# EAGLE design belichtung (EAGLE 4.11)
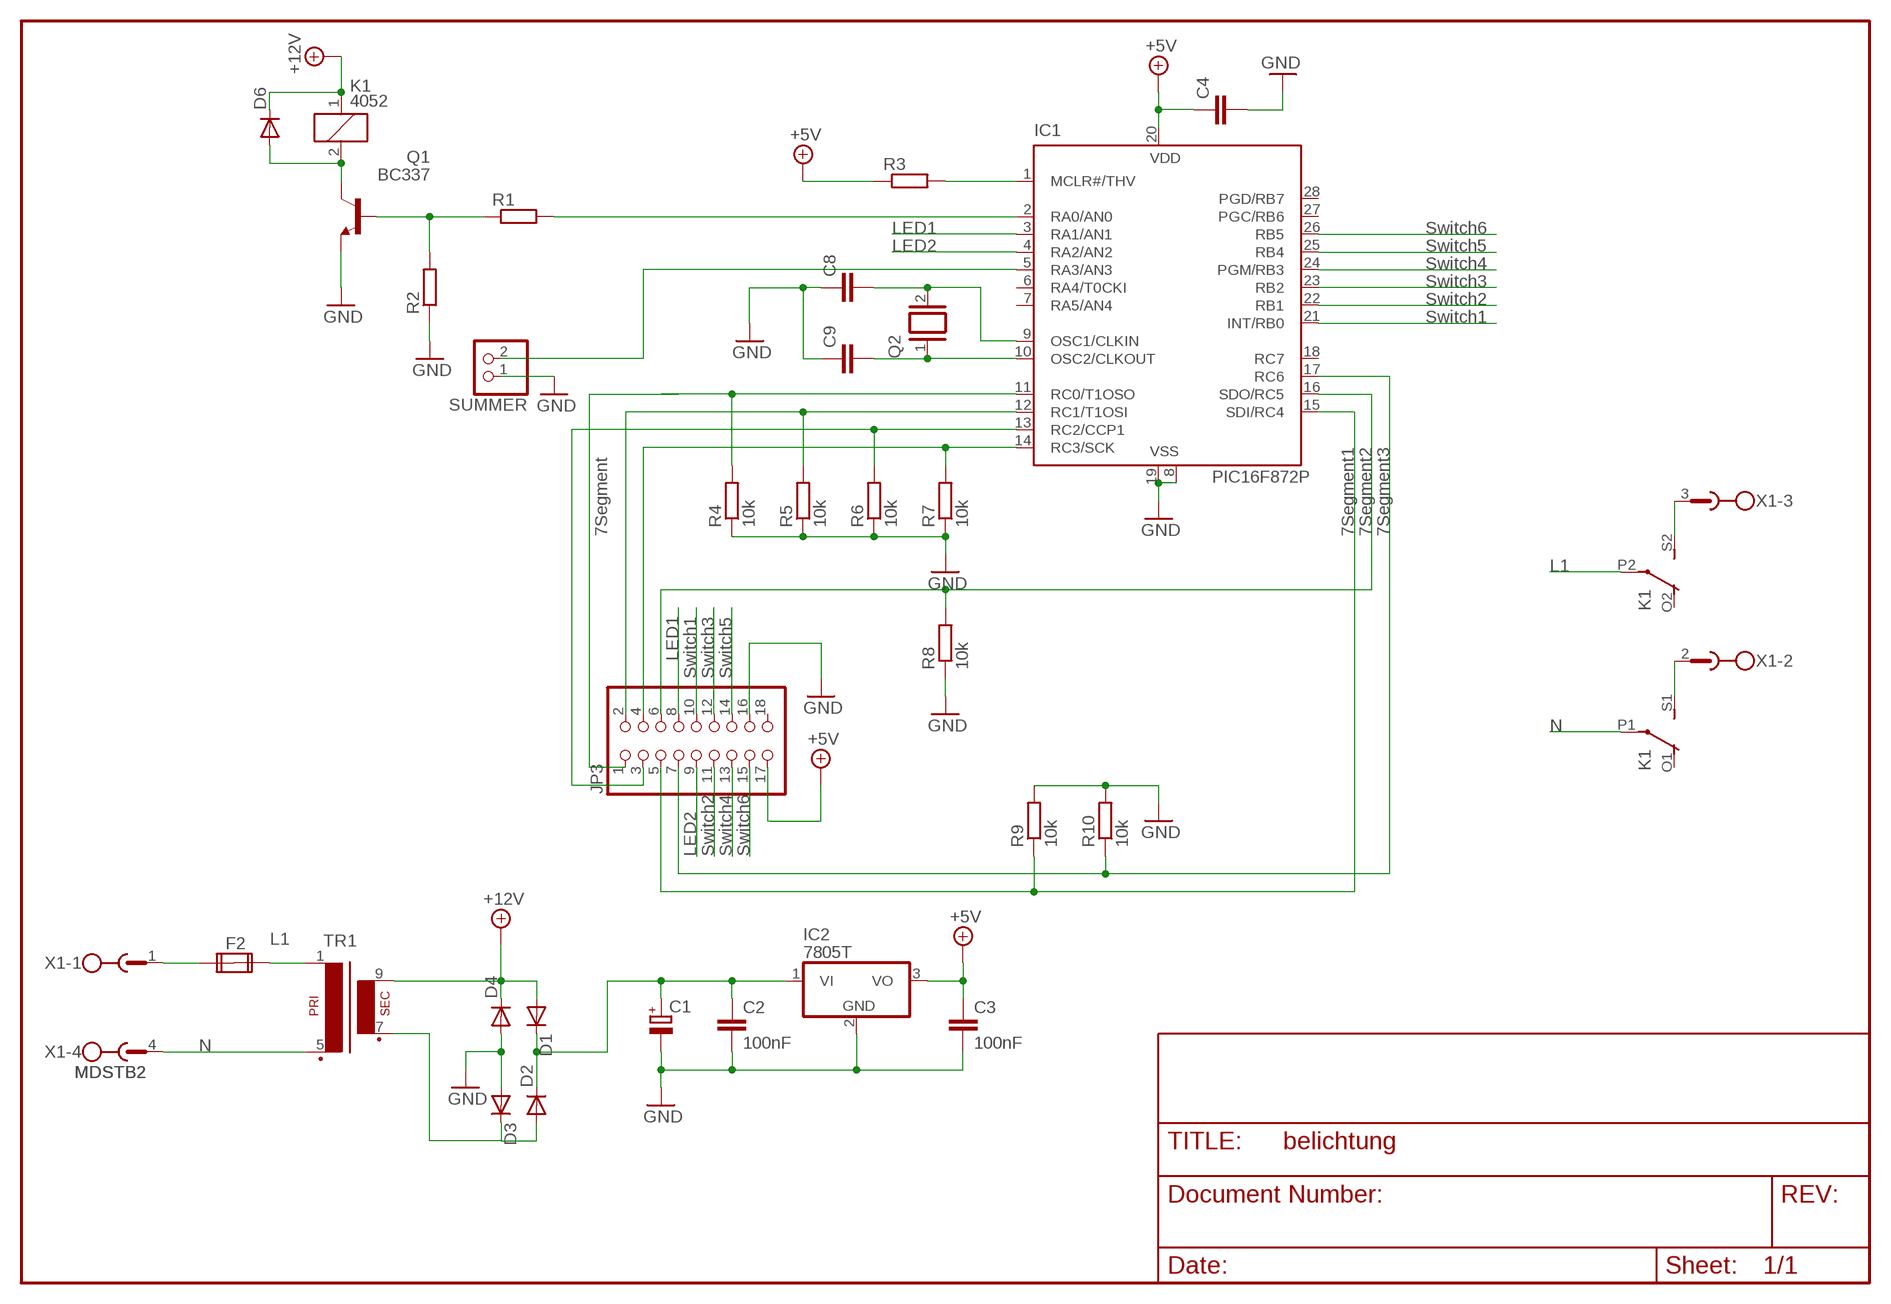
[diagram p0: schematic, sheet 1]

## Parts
C1  CPOL-EUE3.5-8  [E3,5-8]
C2  100nF  C10/4  [C10B4]
C3  100nF  C10/4  [C10B4]
C4  C-EUC1206K  [C1206K]
C8  C-EUC1206K  [C1206K]
C9  C-EUC1206K  [C1206K]
D1  1N4004  [DO41-10]
D2  1N4004  [DO41-10]
D3  1N4004  [DO41-10]
D4  1N4004  [DO41-10]
D6  DIODE-SMB  [SMB]
F2  FUSE2P  [FUSE1]
IC1  PIC16F872P  [DIL28-3]
IC2  7805T  [TO220H]
JP3  PINHD-2X9  [2X09]
K1  4052  [F4052]
Q1  BC337  [TO92]
Q2  XTAL  [Q]
R1  R-EU_0204/7  [0204/7]
R2  R-EU_0204/7  [0204/7]
R3  R-EU_0204/7  [0204/7]
R4  10k  R-EU_R0805  [R0805]
R5  10k  R-EU_0204/7  [0204/7]
R6  10k  R-EU_0204/7  [0204/7]
R7  10k  R-EU_0204/7  [0204/7]
R8  10k  R-EU_R1206  [R1206]
R9  10k  R-EU_0204/2V  [0204V]
R10  10k  R-EU_0204/7  [0204/7]
SUMMER  PINHD-1X2  [1X02]
TR1  EI30-1  [EI30-1]
X1  MDSTB2  [MDSTB2]

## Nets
+5V: C3.1 C4.1 IC1.20(VDD) IC2.3(VO) JP3.17 R3.1
+12V: D1.A D4.C D6.C K1.1 TR1.9
GND: C1.- C2.2 C3.2 C4.2 C8.1 C9.1 D3.A D4.A IC1.8(VSS) IC1.19(VSS) IC2.2(GND) JP3.16 Q1.1(E) R2.1 R4.1 R5.1 R6.1 R7.1 R8.1 R9.2 R10.2 SUMMER.1
IN: F2.1A X1.1
L1: F2.2A K1.P2(3:P) TR1.1
LED1: IC1.3(RA1/AN1) JP3.8
LED2: IC1.4(RA2/AN2) JP3.9
MCLR: IC1.1(MCLR#/THV) R3.2
N: K1.P1(2:P) TR1.5 X1.4
N$1: IC1.11(RC0/T1OSO) JP3.1 R4.2
N$2: Q1.2(B) R1.1 R2.2
N$3: IC1.13(RC2/CCP1) JP3.3 R6.2
N$5: IC1.16(SDO/RC5) JP3.6 R8.2
N$6: IC1.14(RC3/SCK) JP3.4 R7.2
N$7: K1.S1(2:S) X1.2
N$8: IC1.2(RA0/AN0) R1.2
N$10: IC1.15(SDI/RC4) JP3.5 R9.1
N$12: IC1.17(RC6) JP3.7 R10.1
N$19: IC1.5(RA3/AN3) SUMMER.2
N$20: C1.+ C2.1 D1.C D2.C IC2.1(VI)
N$21: IC1.12(RC1/T1OSI) JP3.2 R5.2
N$25: K1.S2(3:S) X1.3
N$27: D2.A D3.C TR1.7
N$29: C9.2 IC1.10(OSC2/CLKOUT) Q2.1
N$30: D6.A K1.2 Q1.3(C)
N$33: C8.2 IC1.9(OSC1/CLKIN) Q2.2
SWITCH1: IC1.21(INT/RB0) JP3.10
SWITCH2: IC1.22(RB1) JP3.11
SWITCH3: IC1.23(RB2) JP3.12
SWITCH4: IC1.24(PGM/RB3) JP3.13
SWITCH5: IC1.25(RB4) JP3.14
SWITCH6: IC1.26(RB5) JP3.15
Unconnected: F2.1B F2.2B IC1.6(RA4/T0CKI) IC1.7(RA5/AN4) IC1.18(RC7) IC1.27(PGC/RB6) IC1.28(PGD/RB7) JP3.18 K1.O1(2:O) K1.O2(3:O)

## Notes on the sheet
- LED1 | Switch6
- LED2 | Switch5
- Switch4
- Switch3
- Switch2
- Switch1
- 7Segment | 7Segment1 | 7Segment2 | 7Segment3
- L1
- LED1
- Switch1 | Switch3 | Switch5
- N
- LED2 | Switch2 | Switch4 | Switch6
- L1
- N

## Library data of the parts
C1 = rcl:CPOL-EU: POLARIZED CAPACITOR, European symbol
C2 C3 = capacitor-wima:C: CAPACITOR
C4 C8 C9 = rcl:C-EU: CAPACITOR, European symbol
D1-D4 = diode:1N4004: DIODE
D6 = diode:DIODE-: DIODE
F2 = special:FUSE2P: FUSE 5 x 20 mm
IC1 = microchip:PIC16*872: MICROCONTROLLER flash type
IC2 = linear:78*: Positive VOLTAGE REGULATOR
JP3 = pinhead:PINHD-2X9: PIN HEADER
K1 = relay:4052: RELAY 2 x switch, Finder
Q1 = transistor-npn:BC337*: NPN Transistor
Q2 = special:XTAL: CRYSTAL
R1-R10 = rcl:R-EU_: RESISTOR, European symbol
SUMMER = pinhead:PINHD-1X2: PIN HEADER
TR1 = trafo:EI30-1: TRANSFORMER 1 primary winding, 1 secondary winding ERA
X1 = con-phoenix-508:MDSTB2: PHOENIX

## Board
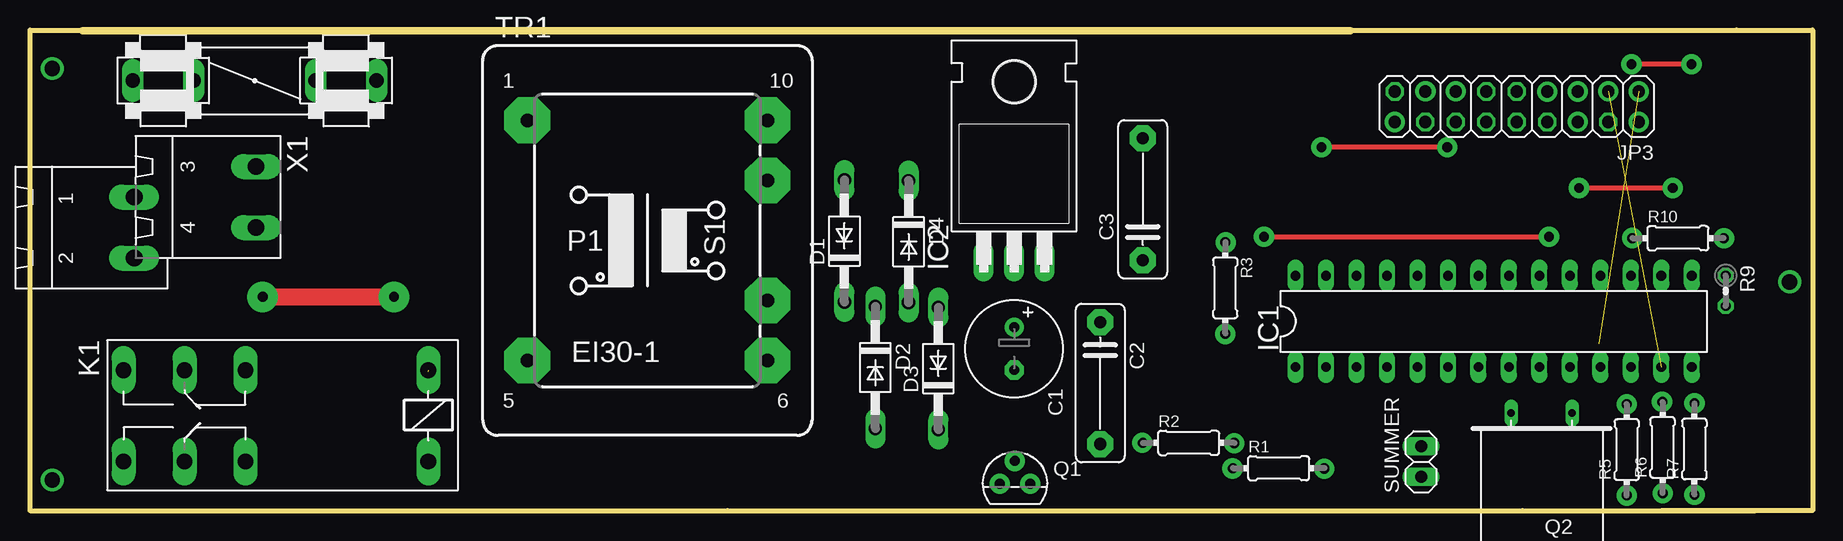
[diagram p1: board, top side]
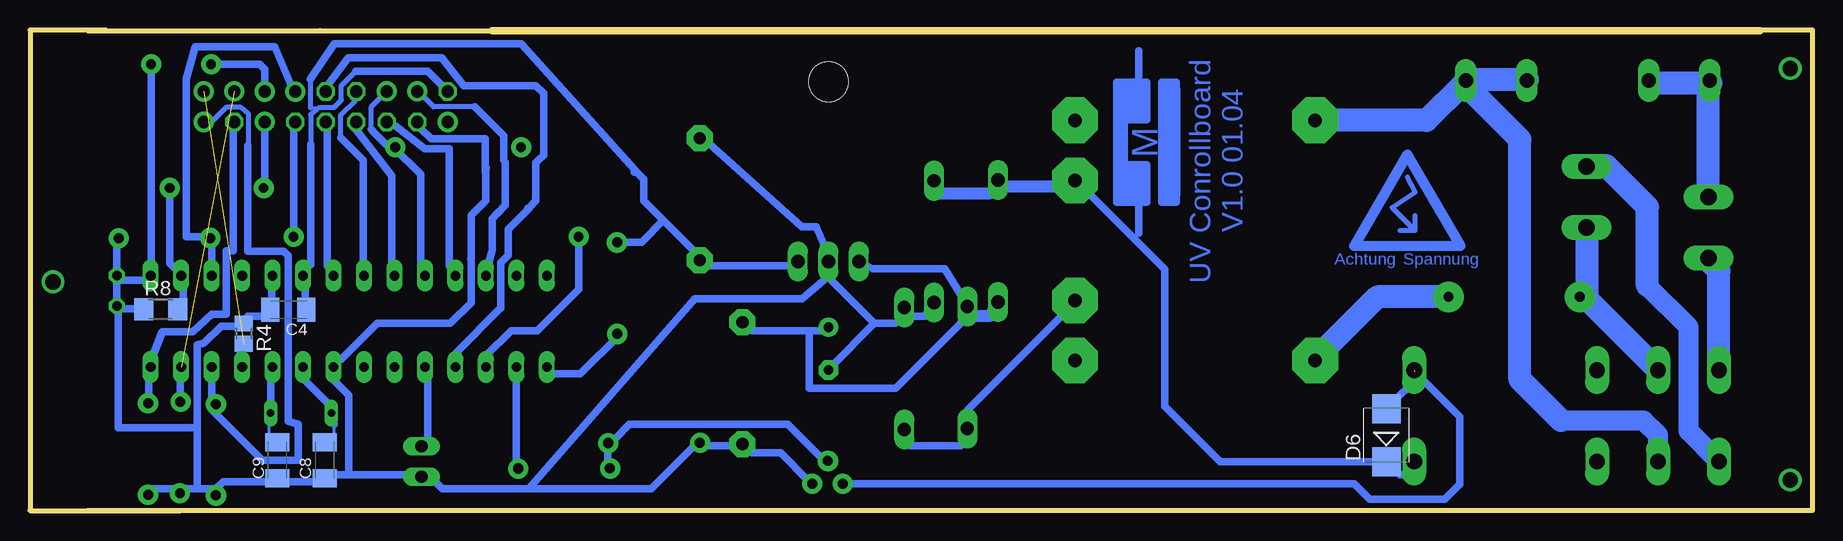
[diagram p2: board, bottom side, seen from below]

Size 148.55 x 40.04 mm. Coordinates in mm from the lower left corner, seen from the top.
Outline: 58.14,0 124.39,0
Outline: 124.39,40 110.02,40
Outline: 110.02,40 4.39,40
Outline: 58.14,0 135.99,0
Outline: 135.99,0 143.77,0
Outline: 143.77,40 110.02,40
Outline: 58.14,0 0,0 0,40.04 6.65,40.04
Outline: 142.23,40.03 148.54,40.03 148.54,0 135.99,0
Copper layers (1*16): Top 0.035mm / dielectric 1.5mm / Bottom 0.035mm
Design rules "default": minimum track width 10mil, minimum drill 24mil, track to track 8mil, track to pad 8mil, pad to pad 8mil, via to via 8mil, smd to smd 8mil, copper to edge 40mil, drill to drill 8mil, minimum pad ring 10mil, minimum via ring 8mil, stop-mask expansion 4mil, vias tented up to drill 0mil, thermal gap 10mil

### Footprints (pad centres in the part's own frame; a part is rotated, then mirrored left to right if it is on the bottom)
E3,5-8 = drill 0.813 pad 1.6 round: + -1.778,0 | drill 0.813 pad 1.6 octagon: - 1.778,0
C10B4 = drill 1.016 pad 2.159 octagon: 1 -5.08,0; 2 5.08,0
C1206K = smd 1.5 x 2: 1 -1.5,0; 2 1.5,0
DO41-10 = drill 1.118 long: A 5.08,0; C -5.08,0
SMB = smd 2.4 x 2.4: A 2.2,0; C -2.2,0
FUSE1 = drill 1.194 long: 1A -10.16,0; 1B -5.08,0; 2A 10.16,0; 2B 5.08,0
DIL28-3 = drill 0.813 long: 1 -16.51,-3.81; 2 -13.97,-3.81; 3 -11.43,-3.81; 4 -8.89,-3.81; 5 -6.35,-3.81; 6 -3.81,-3.81; 7 -1.27,-3.81; 8 1.27,-3.81; 9 3.81,-3.81; 10 6.35,-3.81; 11 8.89,-3.81; 12 11.43,-3.81; 13 13.97,-3.81; 14 16.51,-3.81; 15 16.51,3.81; 16 13.97,3.81; 17 11.43,3.81; 18 8.89,3.81; 19 6.35,3.81; 20 3.81,3.81; 21 1.27,3.81; 22 -1.27,3.81; 23 -3.81,3.81; 24 -6.35,3.81; 25 -8.89,3.81; 26 -11.43,3.81; 27 -13.97,3.81; 28 -16.51,3.81
TO220H = drill 1.118 long: 1 -2.54,-10.16; 2 0,-10.16; 3 2.54,-10.16 | hole 3.302: 0,4.826
2X09 = drill 1.016 octagon: 1 -10.16,-1.27; 2 -10.16,1.27; 3 -7.62,-1.27; 4 -7.62,1.27; 5 -5.08,-1.27; 6 -5.08,1.27; 7 -2.54,-1.27; 8 -2.54,1.27; 9 0,-1.27; 10 0,1.27; 11 2.54,-1.27; 12 2.54,1.27; 13 5.08,-1.27; 14 5.08,1.27; 15 7.62,-1.27; 16 7.62,1.27; 17 10.16,-1.27; 18 10.16,1.27
F4052 = drill 1.321 long: 1 -3.81,3.81; 2 -3.81,-3.81; O1 11.43,-3.81; O2 11.43,3.81; P1 16.51,-3.81; P2 16.51,3.81; S1 21.59,-3.81; S2 21.59,3.81
TO92 = drill 0.813 octagon: 1 1.27,0; 2 0,1.905; 3 -1.27,0
Q = drill 0.61 long: 1 -2.54,-7.62; 2 2.54,-7.62
0204/7 = drill 0.813 octagon: 1 -3.81,0; 2 3.81,0
R0805 = smd 1.3 x 1.5: 1 -0.85,0; 2 0.85,0
R1206 = smd 1.6 x 1.803: 1 -1.422,0; 2 1.422,0
0204V = drill 0.813 octagon: 1 -1.27,0; 2 1.27,0
1X02 = drill 1.016 long: 1 -1.27,0; 2 1.27,0
EI30-1 = drill 1.118 pad 3.81 octagon: 1 -10.008,10.008; 5 -10.008,-10.008; 6 10.008,-10.008; 7 10.008,-5.004; 9 10.008,5.004; 10 10.008,10.008
MDSTB2 = drill 1.397 long: 1 0,-5.08; 2 5.08,-5.08; 3 -2.54,5.08; 4 2.54,5.08

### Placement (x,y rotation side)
C1  82.01,13.48 270 top
C2  [C10B4]  89.18,10.62 270 top
C3  [C10B4]  92.73,25.93 90 top
C4  127.02,16.72 180 bottom
C8  124,4.21 90 bottom
C9  127.92,4.21 90 bottom
D1  67.86,22.45 90 top
D2  70.44,11.93 270 top
D3  75.69,11.82 90 top
D4  73.22,22.41 270 top
D6  35.51,6.27 90 bottom
F2  18.72,35.83 0 top
IC1  121.98,15.77 0 top
IC2  82.01,30.91 0 top
JP3  123.9,33.65 180 top
K1  29.39,7.89 180 top
Q1  82.08,2.23 0 top
Q2  125.96,0.5 180 top
R1  104.05,3.53 0 top
R2  96.55,5.64 0 top
R3  99.6,18.55 270 top
R4  [R0805]  130.72,14.75 270 bottom
R5  [0204/7]  133.06,5.08 90 top
R6  [0204/7]  136.05,5.25 90 top
R7  [0204/7]  138.7,5.13 90 top
R8  [R1206]  137.65,16.77 0 bottom
R9  [0204V]  141.3,18.31 270 top
R10  [0204/7]  137.33,22.7 0 top
SUMMER  115.93,4.08 90 top
TR1  51.45,22.51 0 top
U$1  [ACHTUNGSPANNUNG]  33.76,24.6 0 top
U$2  [LOGO]  55.5,30.71 90 top
X1  13.76,26.12 270 top

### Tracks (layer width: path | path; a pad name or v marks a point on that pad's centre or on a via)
+5V
  Bottom 0.254: C3.1 93.19,21.6 | IC2.3 84.79,20.4 | 125.59,17.4 C4.1 | 125.16,20.4 125.59,20.4 | 114.19,35.4 JP3.17 | 125.18,33.56 124.39,33.6
  Bottom 0.406: 121.39,36.6 122.59,35.4 122.59,34.2 123.19,33.6 124.39,33.6 125.16,33 125.16,20.4 | 125.18,35.96 125.18,33.56
  Bottom 0.61: 93.19,21.6 95.76,24.17 | 95.76,24.17 97.39,25.8 97.39,27.62 98.06,28.28 | 84.79,20.4 91.99,20.4 C3.1 | 125.59,17.4 125.59,18.6 IC1.20 125.59,20.4 | 114.19,35.4 115.39,36.6 121.39,36.6 | 98.06,28.28 98.12,28.34 | 98.06,28.28 97.99,28.2 | 98.12,28.34 107.59,38.89 123.19,38.89 125.18,35.96 | 98.12,28.34 98.18,28.34 98.18,28.2 | 98.06,28.28 | R3.1 97.58,22.36 95.76,24.17
+12V
  Bottom 0.254: 34.39,3 D6.C | 68.59,26.4 D1.A 67.39,27 | 72.79,26.4 D4.C
  Bottom 0.61: 34.39,3 33.79,3 K1.1 | D6.C 49.37,4.07 53.99,8.69 53.99,20.1 61.46,27.57 | 61.46,27.57 61.48,27.59 | 61.46,27.57 TR1.9
  Bottom 1.016: 68.59,26.4 72.79,26.4 | 67.39,27 63.19,27 TR1.9
GND
  Bottom 0.254: 81.79,12 C1.- | 76.39,15.6 D3.A 75.19,16.2 | 81.79,19.2 IC2.2 82.39,19.2 | 139.39,16.8 R8.1 | Q1.1 83.59,2.4 | 92.59,5.4 R2.1 93.19,5.4 | C2.2 90.19,5.4 | 115.99,31.8 JP3.16 | 128.41,17.48 C4.2 128.72,16.2 | 130.39,16.2 R4.1 130.82,15.34 | 138.79,1.8 R7.1 | R6.1 136.39,1.8 | 123.19,3 C8.1 124.99,2.4 | 127.39,2.4 C9.1 128.59,2.4 | 133.06,1.8 R5.1 | IC1.8 122.59,12.6 | 141.19,16.8 R9.2
  Bottom 0.406: 141.07,22.7 140.95,22.81 | 141.07,22.7 R10.2 | 141.3,22.46 141.07,22.7
  Bottom 0.61: 78.19,15.6 81.79,12 | 78.19,15.6 76.39,15.6 | 75.19,16.2 73.99,16.2 D4.A | 81.79,19.2 78.19,15.6 | C3.2 91.99,30.6 84.23,23.64 83.03,23.64 82.39,22.2 IC2.2 | 139.39,16.8 141.19,16.8 141.19,6.92 134.59,6.92 | 83.59,2.4 85.99,4.8 88.39,4.8 C2.2 | 90.19,5.4 92.59,5.4 | 110.59,28.57 110.59,28.2 | 110.59,28.57 110.6,30.99 115.1,30.99 115.99,31.8 | 128.41,17.48 128.41,18.68 IC1.19 | 130.39,16.2 128.72,16.2 | 134.59,1.8 135.79,1.8 R6.1 | 134.59,1.8 133.06,1.8 132.46,2.4 128.59,2.4 | 136.39,1.8 138.79,1.8 | 121.99,3 121.99,9.6 123.19,10.8 IC1.8 | 121.99,3 123.19,3 | 121.99,3 117.19,3 SUMMER.1 114.79,2.4 114.19,1.8 106.99,1.8 | 124.99,2.4 127.39,2.4 | 130.82,15.34 132.62,15.34 134.08,13.93 134.59,13.8 134.59,6.92 | 134.59,1.8 134.59,6.92 | 122.59,12.6 119.59,15.6 113.51,15.6 111.79,17.32 111.79,20.94 111.83,20.98 111.81,21 111.79,21 111.79,24.59 110.58,25.8 | 93.19,5.4 96.79,1.8 106.99,1.8 | 82.39,19.2 84.19,17.65 93.16,17.65 106.99,1.8 | R9.2 141.3,22.46 | 110.58,25.8 110.57,25.82 | 110.58,25.8 110.59,25.8 | 110.54,28.57 | 110.54,28.57 110.59,28.57 | 110.58,25.8 110.58,28.52 110.54,28.57
IN
  Bottom 1.422: F2.1A 8.56,35.73 8.45,35.62 8.68,35.4
  Bottom 1.93: X1.1 8.68,35.4 | 8.45,35.62 13.45,35.62
L1
  Bottom 1.422: F2.2A 28.77,35.94 | F2.2A 29.08,35.62 F2.2A
  Bottom 1.676: K1.P2 12.88,6.3 14.08,7.5 20.95,7.5
  Bottom 1.93: TR1.1 32.19,32.52 29.08,35.62 24.39,30.94 24.39,10.94 20.95,7.5 | 28.77,35.94 23.77,35.94
LED1  (via drill 0.81 pad 1.68)
  Top 0.406: v102.83,22.81 v126.58,22.81
  Bottom 0.406: 126.58,32.5 126.46,32.38 JP3.8
  Bottom 0.61: IC1.3 110.55,12.91 108.45,15 106.27,15 102.83,18.44 v102.83,22.81 | v126.58,22.81 126.58,32.5
LED2
  Bottom 0.254: 123.79,35.4 JP3.9
  Bottom 0.406: 109.39,16.8 109.32,16.87 | 107.05,25.2 106.99,25.2
  Bottom 0.61: 109.39,16.8 112.99,13.2 IC1.4 | 106.99,25.2 106.39,25.8 106.39,28.99 106.16,29.23 106.14,29.23 105.75,29.62 105.75,34.76 106.39,35.4 112.39,35.4 114.23,37.75 122.03,37.75 123.79,35.4 | 109.32,16.87 109.32,20.66 108.7,21.29 108.7,23.44 106.95,25.18 106.96,25.2 107.05,25.2
MCLR
  Bottom 0.61: IC1.1 105.19,11.4 102.67,11.4 99.37,14.7 99.41,14.74 R3.2
N  (via drill 0.81 pad 2.54)
  Top 1.422: v19.39,17.81 v30.33,17.81
  Bottom 1.422: 18.77,23.75 18.77,23.65 X1.4 | 41.44,12.63 TR1.5 | v19.39,17.81 19.08,17.81 12.88,11.61 | 12.88,11.61 12.83,11.56 | K1.P1 12.88,11.61
  Bottom 1.93: K1.P1 18.77,17.59 18.77,23.65 | 41.44,12.63 36.27,17.81 v30.33,17.81
N$1  (1 unrouted)
  Bottom 0.254: 130.99,13.2 130.99,13.8 R4.2
  Bottom 0.61: IC1.11 130.99,13.2
N$2
  Bottom 0.254: Q1.2 82.39,4.2 | 99.79,6 R2.2 100.39,5.4 | 100.39,4.12 R1.1
  Bottom 0.61: 82.39,4.2 85.39,7.2 98.59,7.2 99.79,6 | 100.39,5.4 100.39,4.12
N$3  (1 unrouted)
  Bottom 0.254: R6.2 136.04,9.73 | 136.04,10.93 IC1.13
  Bottom 0.61: 136.04,9.73 136.04,10.93
N$5  (via drill 0.81 pad 1.68)
  Top 0.406: v136.89,26.88 v129.08,26.88
  Bottom 0.254: R8.2 135.79,17.4
  Bottom 0.406: v129.08,26.88 128.98,26.98 | IC1.16 135.95,19.68
  Bottom 0.61: 135.79,17.4 135.79,18.6 IC1.16 | 128.98,26.98 JP3.6 | v136.89,26.88 136.89,20.62 135.95,19.68
N$6
  Bottom 0.254: R7.2 138.65,9.08 | 138.65,10.88 IC1.14 | 131.59,31.8 JP3.4
  Bottom 0.61: 138.65,9.08 138.65,10.88 | 131.59,31.8 131.59,21.65 132.19,21.65 132.19,16.36 133.39,16.36 134.97,14.9 137.54,14.9 138.19,13.2 IC1.14
N$7
  Bottom 1.422: 8.77,20.94 8.68,21.03 X1.2
  Bottom 1.93: K1.S1 7.8,19.97 8.77,20.94
N$8
  Bottom 0.254: R1.2 108.01,4.17
  Bottom 0.61: 108.01,4.17 108.01,10.84 IC1.2
N$9  (via drill 0.81 pad 1.68)
  other vias: 141.16,22.68
N$10  (via drill 0.81 pad 1.68)
  Top 0.406: v138.45,37.19 v133.45,37.19
  Bottom 0.254: IC1.15 138.79,19.2 | 141.19,19.2 R9.1
  Bottom 0.406: 138.45,19.69 138.49,19.66 IC1.15
  Bottom 0.61: 138.79,19.2 141.19,19.2 | JP3.5 128.98,36.77 129.39,37.19 v133.45,37.19 | 138.45,19.69 v138.45,37.19
N$11  (via drill 0.81 pad 1.68)
  other vias: 133.51,22.71
N$12
  Bottom 0.254: 133.39,22.2 R10.1 134.3,22.8 | 126.79,35.4 JP3.7
  Bottom 0.61: 133.39,22.2 133.39,20.4 IC1.17 | 126.79,35.4 128.16,38.64 134.76,38.64 135.51,36 135.51,22.8 134.3,22.8
N$13  (via drill 0.81 pad 1.68)
  other vias: 138.71,8.93
N$14  (via drill 0.81 pad 1.68)
  other vias: 138.71,1.31
N$15  (via drill 0.81 pad 1.68)
  other vias: 136.05,1.43
N$16  (via drill 0.81 pad 1.68)
  other vias: 133.05,1.26
N$17  (via drill 0.81 pad 1.68)
  other vias: 136,9.05
N$18  (via drill 0.81 pad 1.68)
  other vias: 133.05,8.85
N$19
  Bottom 0.61: IC1.5 115.39,10.8 115.39,6 SUMMER.2
N$20
  Bottom 0.254: 69.79,16.2 D2.C
  Bottom 0.61: 83.59,15 88.39,15 C2.1 | 83.59,15 82.39,15 C1.+ | IC2.1 78.33,20.14 72.33,20.14 70.99,18 D2.C 70.99,15.6 76.39,10.2 83.59,10.2 83.59,15
  Bottom 1.016: 69.79,16.2 68.59,16.2 D1.C
N$21
  Bottom 0.254: 133.39,9 R5.2 133.39,8.4 | 133.39,32.4 JP3.2
  Bottom 0.406: 133.39,32.4 132.19,33.6 130.99,33.6 130.33,33.03 130.39,21.6
  Bottom 0.61: 133.39,9 133.39,10.8 IC1.12 | 130.39,21.6 127.39,21.6 127.04,21.25 127.04,7.45 126.19,7.2 126.19,4.2 129.19,4.2 133.39,8.4
N$22  (via drill 0.81 pad 1.68)
  other vias: 99.63,22.34
N$23  (via drill 0.81 pad 1.68)
  other vias: 99.59,14.71
N$24  (via drill 0.81 pad 1.68)
  other vias: 100.35,5.61
N$25
  Bottom 1.422: 19.08,28.75 18.93,28.75 X1.3
  Bottom 1.676: K1.S2 10.33,6.61 10.33,15.31 13.77,18.75
  Bottom 1.93: 13.77,18.75 13.77,25.31 17.2,28.75 18.93,28.75
N$27
  Bottom 0.254: 70.39,8.4 D2.A
  Bottom 0.61: D3.C 75.19,5.4 70.99,5.4 D2.A | 70.39,8.4 62.59,16.2 TR1.7
N$28  (via drill 0.81 pad 1.68)
  other vias: 100.2,3.5
N$29
  Bottom 0.254: C9.2 128.59,6 128.59,7.2 Q2.1 128.47,9
  Bottom 0.61: 128.47,9 128.47,10.8 IC1.10
N$30  (1 unrouted)
  Bottom 0.254: 34.39,9.6 D6.A
  Bottom 0.61: 34.39,9.6 33.79,10.2 K1.2 | Q1.3 38.19,2.23 36.89,0.94 30.64,0.94 29.39,2.19 29.39,7.81 33.14,11.56
N$31  (via drill 0.81 pad 1.68)
  other vias: 107.85,3.47
N$33
  Bottom 0.254: 123.19,7.2 123.19,6 C8.2
  Bottom 0.61: 123.19,7.2 Q2.2 123.79,9 125.59,10.8 IC1.9
N$35  (via drill 0.81 pad 1.68)
  other vias: 92.7,5.63
N$36
  Bottom 0.61: 125.15,30.52 125.16,30.52 125.16,20.48
N$37
  Bottom 0.61: 130.37,21.75 130.38,21.75 130.38,28.83 130.4,28.83 130.4,30.39
N$38  (via drill 1.27)
  other vias: 1.85,2.54
N$39  (via drill 1.27)
  other vias: 1.85,36.83
N$40  (via drill 1.27)
  other vias: 146.63,19.05
N$41  (via drill 0.81 pad 1.68)
  other vias: 80.8,2.23
N$42  (via drill 0.81 pad 1.68)
  other vias: 82.05,4.12
N$43  (via drill 0.81 pad 1.68)
  other vias: 83.35,2.23
N$44  (via drill 0.81 pad 1.68)
  other vias: 134.06,32.38
N$45  (via drill 0.81 pad 1.68)
  other vias: 134.06,34.92
N$46  (via drill 0.81 pad 1.68)
  other vias: 131.52,34.93
N$47  (via drill 0.81 pad 1.68)
  other vias: 128.97,34.92
N$48  (via drill 0.81 pad 1.68)
  other vias: 126.43,34.91
N$49  (via drill 0.81 pad 1.68)
  other vias: 128.97,32.39
N$50  (via drill 0.81 pad 1.68)
  other vias: 113.73,32.38
N$51  (via drill 0.81 pad 1.68)
  other vias: 116.29,34.94
N$52  (via drill 0.81 pad 1.68)
  other vias: 118.82,34.94
N$53  (via drill 0.81 pad 1.42)
  other vias: 113.73,34.91
N$54  (via drill 0.81 pad 1.42)
  other vias: 116.28,32.34
N$55  (via drill 0.81 pad 1.42)
  other vias: 118.81,32.37
N$56  (via drill 0.81 pad 1.42)
  other vias: 121.35,34.92
N$57  (via drill 0.81 pad 1.42)
  other vias: 121.36,32.38
N$58  (via drill 0.81 pad 1.42)
  other vias: 123.9,32.38
N$59  (via drill 0.81 pad 1.42)
  other vias: 123.89,34.93
N$60  (via drill 0.81 pad 1.42)
  other vias: 126.42,32.39
N$61  (via drill 0.81 pad 1.42)
  other vias: 131.54,32.38
SWITCH1
  Bottom 0.254: 123.79,31.8 JP3.10
  Bottom 0.61: 123.79,31.8 123.79,20.4 IC1.21
SWITCH2
  Bottom 0.406: 122.63,31.09 122.63,33 121.39,34.2 JP3.11
  Bottom 0.61: 122.63,31.09 120.79,29.2 120.79,20.4 IC1.22
SWITCH3
  Bottom 0.254: 121.39,31.8 JP3.12
  Bottom 0.61: 121.39,31.8 121.39,31.79 118.39,27.88 118.39,20.4 IC1.23
SWITCH4  (via drill 0.61, 0.81 pad 1.68)
  Top 0.406: v107.62,30.27 v118.1,30.27 v118.12,30.29
  Bottom 0.406: v107.62,30.27 107.64,30.24 | v118.12,30.29 118.3,30.47 | 120.11,31.77 120.11,33.63 JP3.13
  Bottom 0.61: IC1.24 115.99,20.4 115.99,28.01 118.22,30.23 118.18,30.27 v118.1,30.27 | 118.3,30.47 118.84,30.47 119.99,31.62 119.99,31.66 120.11,31.77 | JP3.13
SWITCH5
  Bottom 0.254: 118.11,32.07 JP3.14
  Bottom 0.61: 118.11,32.07 115.65,30.17 113.59,30.17 113.59,20.4 IC1.25
SWITCH6
  Bottom 0.406: JP3.15 116.19,34.92 114.9,33.64 111.5,33.64 | 110.08,21.58 110.04,21.71 | 110.64,19.56 110.63,19.57 IC1.26
  Bottom 0.61: 110.08,21.58 110.28,20.76 110.28,19.93 110.63,19.57 | 109.61,24.76 109.43,24.93 | 109.61,24.76 109.61,24.75 108.93,25.43 108.93,29.04 109.08,29.2 109.08,31.22 111.5,33.64 | 110.04,21.71 110.04,24.32 109.61,24.76

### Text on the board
Bottom: UV Conrollboard | V1.0 01.04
